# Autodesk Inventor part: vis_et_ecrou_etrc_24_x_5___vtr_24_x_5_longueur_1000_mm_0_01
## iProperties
Shininess: 20.0
Length Units: 11269
Angle Units: 11279
Time Units: 11290
Mass Units: 11283
Length Display Precision: 3
Angle Display Precision: 2
Created: 2005-02
Part Number: vis_et_ecrou_etrc_24_x_5___vtr_24_x_5_longueur_1000_mm_0_01
Material: Par défaut
Document SubType Name: Modélisation
Designer: ytiennot
Density: 0.0
Volumn: 0.0
Area: 0.0
PropertySet Name: Model Information
Control State: 0
Master: False
Checked Out: False
Author: ytiennot
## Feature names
1. Base1
